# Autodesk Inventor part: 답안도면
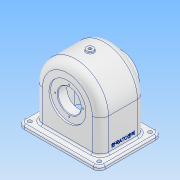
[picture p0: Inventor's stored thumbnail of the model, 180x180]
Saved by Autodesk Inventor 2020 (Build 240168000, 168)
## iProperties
Created: 2022-09
Part Number: 답안도면
Material: 알루미늄 6061
Document SubType Name: Modeling
Designer: user
Density: 2.7 g/cm^3
Appearance: 알루미늄 - 평지
Mass: 788.738 g
Surface Area: 1041.96 cm^2
Volume: 292.125 cm^3
Author: user
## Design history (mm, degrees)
sketch "스케치1"
  geometry: L1 (70, 54)-(-70, 54); L2 (-70, 54)-(-70, -54); L3 (-70, -54)-(70, -54); L4 (70, -54)-(70, 54); L5 (70, 54)-(-70, -54); L6 (-70, 54)-(70, -54); 1 further point
  constraints: 12 end point, 2 midpoint, 2 parallel, 1 horizontal, 1 perpendicular
  dimensions: "d0" = 140 distance of L2.end L3.end; "d1" = 108 distance of L3.end L1.start
extrude "돌출1" new body sketch "스케치1" distance "d2" = 7; taper "d3" = 0 deg
sketch "스케치2"
  geometry: L1 (-70, 0)-(-70, 7) reference; L2 (-70, 7)-(70, 7) reference; L3 (70, 7)-(70, 0) reference; L4 (70, 0)-(-70, 0) reference; L5 (0, 0)-(0, 64); L6 (-57, 64)-(-57, 0); L7 (57, 64)-(57, 0); A1 r 57 centre (0, 64) between (-57, 64) and (57, 64); 2 further points
  constraints: 6 end point, 2 perpendicular, 2 point on circle, 2 point on line, 2 tangent, 1 centre point, 1 coincident, 1 vertical
  dimensions: "d4" = 64 distance of L5.start L5.end; "d5" = 114 diameter of A1
extrude "돌출2" join sketch "스케치2" stored distance "d6" = 78; taper "d7" = 0 deg
sketch "스케치3"
  geometry: L1 (57, 7)-(-57, 7) reference; L2 (57, 7)-(57, 64) reference; L3 (-57, 64)-(-57, 7) reference; C1 r 31 at (0, 64); A1 r 57 centre (0, 64) between (57, 64) and (-57, 64) reference; 1 further point
  constraints: 1 centre point, 1 coincident
  dimensions: "d8" = 62 diameter of C1
extrude "돌출3" join sketch "스케치3" distance "d9" = 15; taper "d10" = 0 deg
node "작업 평면1"
sketch "스케치4"
  geometry: L1 (-70, -54)-(-70, 54) reference; L2 (-70, 54)-(70, 54) reference; C1 r 6 at (0, 0); 3 further points
  constraints: 2 midpoint, 1 centre point, 1 coincident, 1 horizontal alignment, 1 vertical alignment
  dimensions: "d12" = 12 diameter of C1
extrude "돌출4" join sketch "스케치4" distance "d13" = 20; taper "d14" = 0 deg
sketch "스케치6"
  geometry: L1 (-70, 0)-(-70, 7) reference; L2 (-70, 7)-(-57, 7) reference; L3 (-57, 7)-(-57, 64) reference; L4 (-6, 120.683)-(-6, 124) reference; L5 (-6, 124)-(6, 124) reference; L6 (6, 124)-(6, 120.683) reference; L7 (57, 64)-(57, 7) reference; L8 (57, 7)-(70, 7) reference; L9 (70, 7)-(70, 0) reference; L10 (70, 0)-(-70, 0) reference; L11 (-52, 64)-(-52, 5); L12 (52, 5)-(52, 64); L13 (-52, 5)-(-52, 0); L14 (52, 5)-(52, 0); A1 r 57 centre (0, 64) between (-6, 120.683) and (-57, 64) reference; A2 r 57 centre (0, 64) between (57, 64) and (6, 120.683) reference; A3 r 52 centre (0, 64) between (52, 64) and (-52, 64); A4 r 52 centre (0, 64) between (52, 64) and (1, 115.99); 1 further point
  constraints: 8 end point, 4 point on circle, 2 centre point, 2 perpendicular, 2 point on line, 1 other
  dimensions: "d19" = 5 radial gap between concentric circles of A2 A4
  node "절단 모서리 투영3"
extrude "돌출5" cut sketch "스케치6" distance "d20" = 34; taper "d21" = 0 deg
extrude "돌출6" cut sketch "스케치6" distance "d22" = 20; taper "d23" = 0 deg
sketch "스케치8"
  geometry: L1 (0, 54)-(7, 54) reference; L2 (7, 54)-(7, 39) reference; L3 (7, 39)-(121, 39) reference; L4 (121, 39)-(121, 6) reference; L5 (121, 6)-(124, 6) reference; L6 (124, 6)-(124, -6) reference; L7 (124, -6)-(121, -6) reference; L8 (121, -6)-(121, -39) reference; L9 (121, -39)-(95, -39) reference; L10 (95, -39)-(95, -54) reference; L11 (95, -54)-(33, -54) reference; L12 (33, -54)-(33, -39) reference; L13 (33, -39)-(7, -39) reference; L14 (7, -39)-(7, -54) reference; L15 (7, -54)-(0, -54) reference; L16 (0, -54)-(0, -34) reference; L17 (0, -34)-(116, -34) reference; L18 (116, -34)-(116, 20) reference; L19 (116, 20)-(0, 20) reference; L20 (0, 20)-(0, 54) reference; L21 (36, 20)-(27.917, 34); L22 (27.917, 34)-(0, 34); L23 (64, 55.465)-(64, -74.879); L24 (0, -34)-(0, 20) reference; 1 further point
  constraints: 6 end point, 2 point on line, 1 perpendicular, 1 vertical
  dimensions: "d33" = 64 distance between parallel lines of L24 L23; "d34" = 120 deg angle of L19 L21; "d35" = 14 distance between parallel lines of L19 L22; "d36" = 28 distance from line of L21.start L23
extrude "돌출7" cut sketch "스케치8" stored distance "d37" = 104; taper "d38" = 0 deg
sketch "스케치9"
  geometry: L1 (0, 54)-(7, 54) reference; L2 (7, 54)-(7, 39) reference; L3 (7, 39)-(121, 39) reference; L4 (121, 39)-(121, 6) reference; L5 (121, 6)-(124, 6) reference; L6 (124, 6)-(124, -6) reference; L7 (124, -6)-(121, -6) reference; L8 (121, -6)-(121, -39) reference; L9 (121, -39)-(95, -39) reference; L10 (95, -39)-(95, -54) reference; L11 (95, -54)-(33, -54) reference; L12 (33, -54)-(33, -39) reference; L13 (33, -39)-(7, -39) reference; L14 (7, -39)-(7, -54) reference; L15 (7, -54)-(0, -54) reference; L16 (0, -54)-(0, -34) reference; L17 (0, -34)-(116, -34) reference; L18 (116, -34)-(116, 20) reference; L19 (116, 20)-(36, 20) reference; L20 (36, 20)-(27.917, 34) reference; L21 (27.917, 34)-(0, 34) reference; L22 (0, 34)-(0, 54) reference; L23 (116, 20)-(116, 34); L24 (116, 34)-(100.083, 34); L25 (100.083, 34)-(92, 20); L26 (64, 65.514)-(64, -74.237); 1 further point
  constraints: 8 end point, 2 vertical, 1 perpendicular, 1 point on line
  dimensions: "d39" = 64 distance between parallel lines of L16 L26; "d40" = 14 distance of L18.end L23.end; "d41" = 28 distance from line of L26 L25.end; "d42" = 60 deg angle of L19 L25
revolve "회전1" sketch "스케치9" stored, may be unused: angle "d43" = 180 deg
sketch "스케치10"
  geometry: L1 (0, 54)-(7, 54) reference; L2 (7, 54)-(7, 39) reference; L3 (7, 39)-(121, 39) reference; L4 (121, 39)-(121, 6) reference; L5 (121, 6)-(124, 6) reference; L6 (124, 6)-(124, -6) reference; L7 (124, -6)-(121, -6) reference; L8 (121, -6)-(121, -39) reference; L9 (121, -39)-(95, -39) reference; L10 (95, -39)-(95, -54) reference; L11 (95, -54)-(33, -54) reference; L12 (33, -54)-(33, -39) reference; L13 (33, -39)-(7, -39) reference; L14 (7, -39)-(7, -54) reference; L15 (7, -54)-(0, -54) reference; L16 (0, -54)-(0, -34) reference; L17 (0, -34)-(116, -34) reference; L18 (116, -34)-(116, 34) reference; L19 (116, 34)-(100.083, 34) reference; L20 (100.083, 34)-(92, 20) reference; L21 (92, 20)-(36, 20) reference; L22 (36, 20)-(27.917, 34) reference; L23 (27.917, 34)-(0, 34) reference; L24 (0, 34)-(0, 54) reference; L25 (64, 57.534)-(64, -78.957); L26 (96, 39)-(96, 36); L27 (96, 36)-(84, 36); L28 (84, 36)-(84, 20); L29 (84, -54)-(84, -38); L30 (84, -38)-(81.5, -38); L31 (81.5, -38)-(81.5, -34); 5 further points
  constraints: 14 end point, 6 perpendicular, 4 point on line, 1 vertical
  dimensions: "d44" = 128 diameter of L16 L25; "d45" = 16 distance of L27.end L28.end; "d46" = 64 diameter of L26 L25; "d47" = 40 diameter of L28 L25; "d48" = 16 distance of L29.start L29.end; "d49" = 40 diameter of L29 L25; "d50" = 35 diameter of L31 L25
revolve "회전2" sketch "스케치10" stored, may be unused: angle "d51" = 180 deg
node "작업 평면2"
sketch "스케치11"
  geometry: L1 (-15, -7)-(-15, 0) reference; L2 (-15, 0)-(0, 0) reference; L3 (0, 0)-(0, 80.345) reference; L4 (0, 80.345)-(78, 80.345) reference; L5 (78, 80.345)-(78, 0) reference; L6 (78, 0)-(93, 0) reference; L7 (93, 0)-(93, -7) reference; L8 (93, -7)-(73, -7) reference; L9 (73, -7)-(5, -7) reference; L10 (5, -7)-(-15, -7) reference; L11 (73, -7)-(73, 57) reference; L12 (73, 57)-(19, 57) reference; L13 (19, 57)-(19, 29) reference; L14 (19, 29)-(5, 20.917) reference; L15 (5, 20.917)-(5, -7) reference; L16 (19, 57)-(5, 57) reference; L17 (5, -7)-(5, 57); 2 further points
  constraints: 2 end point, 1 vertical
extrude "돌출8" cut sketch "스케치11" distance "d53" = 14.75; taper "d54" = 0 deg
node "작업 평면3"
sketch "스케치12"
  geometry: L1 (15, 0)-(15, -7) reference; L2 (15, -7)-(-5, -7) reference; L3 (-5, -7)-(-5, 20.917) reference; L4 (-5, 20.917)-(-19, 29) reference; L5 (-19, 29)-(-19, 57) reference; L6 (-73, 57)-(-19, 57) reference; L7 (-73, 57)-(-73, -7) reference; L8 (-73, -7)-(-93, -7) reference; L9 (-93, -7)-(-93, 0) reference; L10 (-93, 0)-(-78, 0) reference; L11 (-78, 0)-(-78, 80.345) reference; L12 (-78, 80.345)-(0, 80.345) reference; L13 (0, 80.345)-(0, 0) reference; L14 (0, 0)-(15, 0) reference; L15 (-5, -7)-(-73, -7) reference; L16 (-19, 57)-(-5, 57) reference; L17 (-19, 57)-(-19, -7); L18 (-19, 57)-(-5, 57); L19 (-5, 57)-(-5, -7); 2 further points
  constraints: 6 end point, 2 point on line, 1 collinear, 1 vertical
extrude "돌출9" cut sketch "스케치12" distance "d56" = 15.5; taper "d57" = 0 deg
fillet "모깎기2" dims "d59" = 14
fillet "모깎기3" dims "d60" = 3
fillet "모깎기4" dims "d61" = 3
fillet "모깎기5" dims "d62" = 1
sketch "스케치13"
  geometry: 1 further point
sketch "스케치14"
  geometry: C1 r 6 at (0, 0) reference; 2 further points
  constraints: 1 coincident
hole "구멍1" sketch "스케치14" at (0, 0) diameter "d63" = 5.1881; stored, may be unused: countersink angle "d67" = 90 deg, drill point angle "d69" = 118 deg; dims "d64" = 43.75, "d65" = 8, "d66" = 4.4, "d68" = 56.03262
sketch "스케치15" dims "d70" = 48
  geometry: L1 (55.961, -57)-(70, -57) reference; L2 (70, -57)-(70, -64) reference; L3 (70, -64)-(-70, -64) reference; L4 (-70, -64)-(-70, -57) reference; L5 (-70, -57)-(-55.961, -57) reference; L6 (-51.66, -54)-(-51.66, 0) reference; L7 (51.66, 0)-(51.66, -54) reference; C1 r 20 at (0, 0) reference; C2 r 32 at (0, 0) reference; A1 r 51.66 centre (0, 0) between (51.66, 0) and (-51.66, 0) reference; 3 further points
  constraints: 2 vertical alignment, 1 coincident, 4 other
hole "구멍2" sketch "스케치15" at (0, 24) diameter "d71" = 2.459; stored, may be unused: countersink angle "d75" = 90 deg, drill point angle "d77" = 118 deg; dims "d72" = 7, "d73" = 8, "d74" = 4.4, "d76" = 9
sketch "스케치16" dims "d81" = 48
  geometry: L1 (-70, -57)-(70, -57) reference; L2 (70, -57)-(70, -64) reference; L3 (70, -64)-(-70, -64) reference; L4 (-70, -64)-(-70, -57) reference; C1 r 31 at (0, 0) reference; C2 r 20 at (0, 0) reference; 3 further points
  constraints: 2 vertical alignment, 1 coincident, 2 other
hole "구멍3" sketch "스케치16" at (0, 24) diameter "d82" = 2.459; stored, may be unused: countersink angle "d86" = 90 deg, drill point angle "d88" = 118 deg; dims "d83" = 7, "d84" = 8, "d85" = 4.4, "d87" = 9
fillet "모깎기6" dims "d92" = 9
fillet "모깎기7" dims "d93" = 9
fillet "모깎기8" dims "d94" = 0.6
chamfer "모따기1" distance "d95" = 1; stored, may be unused: second distance "d96" = 2, angle "d97" = 45 deg
chamfer "모따기2" distance "d98" = 1; stored, may be unused: second distance "d99" = 2, angle "d100" = 45 deg
fillet "모깎기9" dims "d101" = 3
sketch "스케치17"
  geometry: L1 (-14, 0)-(-14, -54) reference; 2 further points
  constraints: 1 other
  dimensions: "d102" = 17 distance of point (25, -64) point (25, -47); "d103" = 39 distance from line of L1 point (25, -47)
feature "엠보싱1" sketch "스케치17" dims "d104" = 0.5, "d105" = 0
fillet "모깎기10" dims "d106" = 10
sketch "스케치18"
  geometry: L1 (-70, 44)-(-70, -44) reference; L2 (60, 54)-(-60, 54) reference; L3 (70, -44)-(70, 44) reference; L4 (-60, -54)-(60, -54) reference; L5 (-70, 44)-(-70, -44) reference; L6 (52, -25)-(52, 25) reference; L7 (43, 34)-(-43, 34) reference; L8 (-52, 25)-(-52, -25) reference; L9 (-43, -34)-(43, -34) reference; A1 r 10 centre (-60, 44) between (-60, 54) and (-70, 44) reference; A2 r 10 centre (60, 44) between (70, 44) and (60, 54) reference; A3 r 10 centre (60, -44) between (60, -54) and (70, -44) reference; A4 r 10 centre (-60, -44) between (-70, -44) and (-60, -54) reference; A5 r 9 centre (43, 25) between (52, 25) and (43, 34) reference; A6 r 9 centre (-43, 25) between (-43, 34) and (-52, 25) reference; A7 r 9 centre (-43, -25) between (-52, -25) and (-43, -34) reference; A8 r 9 centre (43, -25) between (43, -34) and (52, -25) reference; 5 further points
  constraints: 4 coincident
hole "구멍4" sketch "스케치18" at (-60, -44), (-60, 44), (60, 44), (60, -44) diameter "d107" = 6.6; stored, may be unused: countersink angle "d111" = 90 deg, drill point angle "d113" = 0 deg; dims "d108" = 6.6, "d109" = 8, "d110" = 4.4, "d112" = 13
fillet "모깎기11" dims "d114" = 3
node "솔리드1"
pattern_circular "원형 패턴1" dims angle "d79" = 360 deg
pattern_circular "원형 패턴2" dims angle "d90" = 360 deg
node "투영된 루프1"
node "투영된 루프2"
node "절단 모서리 투영1"
node "절단 모서리 투영5"
node "절단 모서리 투영6"
node "절단 모서리 투영7"
node "절단 모서리 투영8"
node "절단 모서리 투영9"
node "절단 모서리 투영10"
node "절단 모서리 투영11"
feature "A9D066F2-1C7D-4E18-AEED-F7BC21143FA4" dims "d107" = 6.6, "d108" = 6.6, "d109" = 8, "d110" = 4.4, "d111" = 90 deg, "d112" = 13, "d113" = 0
other parameters: "d11" = -124, "d52" = -5, "d55" = -5
